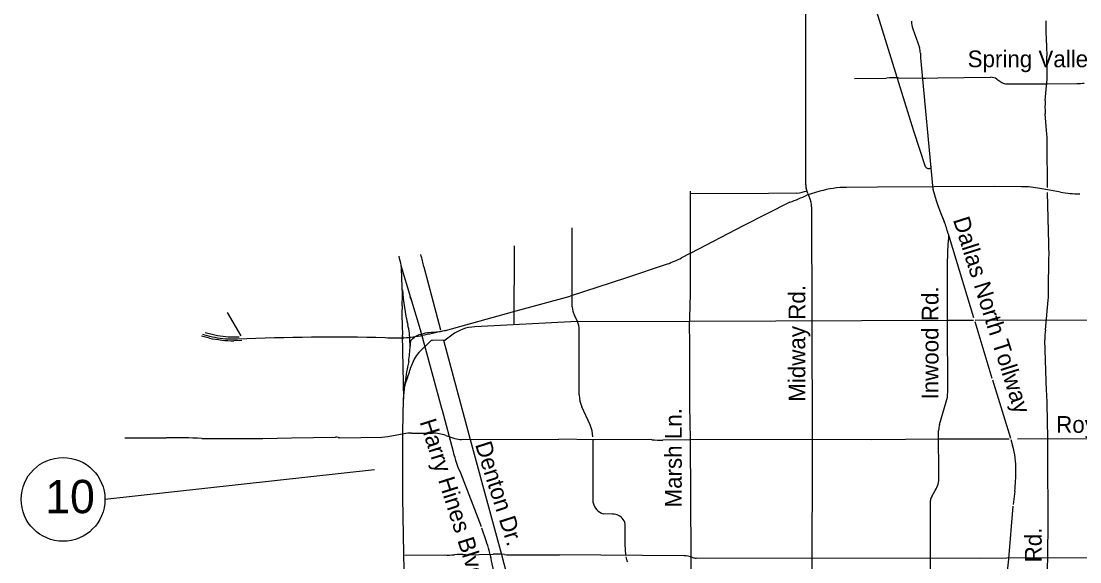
# Model space of a CAD drawing. Extents: x 105094 to 105814, y -291615 to -291123.
# Drawn here: x 105371.4 to 105448.1, y -291407.7 to -291368.5 of the extents above; entities that cross this region are included whole.
import ezdxf

# ---------------------------------------------------------------- set-up
doc = ezdxf.new("R2010")
doc.units = 0
doc.layers.add('G_BORDER', color=7, linetype='Continuous')
doc.layers.add('G_MAP', color=7, linetype='Continuous')

msp = doc.modelspace()

# ---------------------------------------------------------------- linework, layer by layer
at = {"layer": 'G_BORDER'}
msp.add_line((105396.969, -291401.024), (105377.435, -291403.157), dxfattribs=at)
msp.add_circle((105374.4, -291403.157), 3.035, dxfattribs=at)
at = {"layer": 'G_MAP'}
for p, q in [((105428.23, -291378.214), (105428.23, -291362.41)), ((105445.671, -291369), (105445.668, -291368.473)), ((105435.989, -291369.057), (105436.471, -291370.416)), ((105445.691, -291370.072), (105445.671, -291369)), ((105436.542, -291370.831), (105436.542, -291371.168)), ((105445.736, -291372.229), (105445.717, -291371.047)), ((105436.542, -291371.168), (105437.459, -291380.687)), ((105431.759, -291372.656), (105434.1, -291372.623)), ((105434.959, -291372.617), (105436.723, -291372.644)), ((105442.086, -291372.703), (105442.453, -291372.941)), ((105442.824, -291373.05), (105445.762, -291373.043)), ((105445.597, -291374.249), (105445.717, -291372.927)), ((105445.762, -291373.043), (105447.896, -291373.024)), ((105445.688, -291376.421), (105445.592, -291375.214)), ((105445.768, -291380.548), (105445.742, -291377.38)), ((105419.848, -291380.822), (105419.849, -291381.654)), ((105428.387, -291381.004), (105428.268, -291380.597)), ((105429.253, -291380.831), (105428.326, -291381.117)), ((105428.387, -291381.004), (105428.601, -291381.569)), ((105433.435, -291380.536), (105431.191, -291380.549)), ((105437.549, -291380.51), (105433.435, -291380.536)), ((105437.459, -291380.687), (105437.698, -291381.488)), ((105441.938, -291380.484), (105437.549, -291380.51)), ((105443.883, -291380.497), (105441.938, -291380.484)), ((105445.894, -291380.762), (105445.215, -291380.635)), ((105445.846, -291384.63), (105445.768, -291380.917)), ((105446.696, -291380.9), (105445.894, -291380.762)), ((105419.849, -291381.654), (105419.862, -291385.122)), ((105427.086, -291381.628), (105423.708, -291383.33)), ((105428.646, -291381.97), (105428.701, -291398.615)), ((105423.708, -291383.33), (105419.91, -291385.306)), ((105411.314, -291388.426), (105411.295, -291383.484)), ((105438.563, -291383.908), (105438.628, -291384.149)), ((105438.628, -291384.149), (105440.398, -291389.982)), ((105419.823, -291385.345), (105419.235, -291385.653)), ((105398.896, -291386.209), (105400.275, -291390.842)), ((105400.549, -291386.304), (105401.761, -291390.861)), ((105418.19, -291386.101), (105415.173, -291387.118)), ((105445.842, -291387.925), (105445.862, -291385.783)), ((105415.173, -291387.118), (105411.159, -291388.42)), ((105406.983, -291389.569), (105411.159, -291388.42)), ((105411.31, -291389.204), (105411.314, -291388.426)), ((105445.61, -291390.863), (105445.804, -291388.729)), ((105387.321, -291391.313), (105386.31, -291389.615)), ((105398.969, -291389.798), (105398.986, -291390.554)), ((105402.122, -291390.916), (105406.983, -291389.569)), ((105411.693, -291390.265), (105411.482, -291389.808)), ((105440.514, -291390.176), (105449.211, -291390.156)), ((105398.986, -291390.554), (105398.999, -291391.223)), ((105399.358, -291390.38), (105399.342, -291390.273)), ((105400.275, -291390.842), (105401.832, -291396.545)), ((105400.307, -291390.961), (105400.34, -291391.097)), ((105401.783, -291390.945), (105401.803, -291391.016)), ((105411.675, -291390.26), (105404.246, -291390.647)), ((105411.821, -291395.591), (105411.821, -291390.846)), ((105440.488, -291390.269), (105441.732, -291394.374)), ((105385.022, -291391.468), (105384.424, -291391.322)), ((105384.703, -291391.07), (105385.4, -291391.242)), ((105387.363, -291391.655), (105386.785, -291391.668)), ((105386.94, -291391.387), (105387.16, -291391.381)), ((105398.99, -291391.242), (105399.071, -291395.889)), ((105399.006, -291391.332), (105399.006, -291391.552)), ((105399.561, -291392.024), (105399.503, -291391.122)), ((105401.031, -291391.697), (105400.183, -291392.522)), ((105400.385, -291391.226), (105400.42, -291391.355)), ((105402.064, -291391.623), (105401.169, -291391.639)), ((105402.583, -291391.25), (105402.107, -291391.608)), ((105445.697, -291395.291), (105445.565, -291391.59)), ((105399.845, -291393.003), (105399.695, -291393.332)), ((105399.071, -291395.889), (105399.206, -291394.67)), ((105399.377, -291394.318), (105399.246, -291394.633)), ((105441.77, -291394.49), (105443.072, -291398.73)), ((105399.038, -291398.273), (105399.071, -291395.889)), ((105437.931, -291397.739), (105438.423, -291396.093)), ((105401.832, -291396.545), (105401.88, -291396.7)), ((105401.88, -291396.7), (105402.672, -291399.684)), ((105412.6, -291397.761), (105412.009, -291396.46)), ((105399.035, -291403.017), (105399.038, -291398.273)), ((105399.65, -291398.35), (105401.185, -291398.357)), ((105402.147, -291398.518), (105402.801, -291398.74)), ((105428.701, -291398.615), (105428.704, -291398.779)), ((105437.886, -291401.553), (105437.869, -291398.156)), ((105403.282, -291398.819), (105410.339, -291398.786)), ((105412.828, -291403.411), (105412.815, -291398.828)), ((105428.704, -291398.776), (105428.685, -291410.46)), ((105443.104, -291398.821), (105443.231, -291399.257)), ((105437.366, -291402.94), (105437.627, -291402.509)), ((105399.094, -291407.102), (105399.035, -291403.017)), ((105437.282, -291410.389), (105437.282, -291403.244)), ((105443.385, -291402.558), (105443.269, -291403.539)), ((105443.256, -291403.655), (105442.932, -291407.466)), ((105414.233, -291404.218), (105413.558, -291404.215)), ((105405.068, -291406.149), (105404.755, -291405.236)), ((105399.162, -291410.487), (105399.094, -291407.102)), ((105403.573, -291407.164), (105405.577, -291407.122)), ((105399.168, -291407.196), (105402.032, -291407.183)), ((105406.14, -291410.645), (105405.459, -291407.609)), ((105407.106, -291407.176), (105410.377, -291407.173)), ((105419.396, -291407.241), (105410.377, -291407.173)), ((105442.933, -291407.489), (105442.544, -291410.814)), ((105450.086, -291407.395), (105442.801, -291407.424))]:
    msp.add_line(p, q, dxfattribs=at)
for points in [[(105436.913, -291379.063), (105436.064, -291376.473), (105432.285, -291364.23)], [(105436.888, -291372.631), (105437.821, -291372.62), (105441.637, -291372.574)], [(105428.236, -291380.358), (105428.23, -291378.214)], [(105427.596, -291380.964), (105425.529, -291380.998), (105419.849, -291381.024)], [(105437.879, -291382.066), (105438.082, -291382.554), (105438.279, -291383.022)], [(105407.109, -291384.786), (105407.07, -291390.499)], [(105419.862, -291385.122), (105419.855, -291388.167), (105419.833, -291389.194), (105419.797, -291390.586), (105419.804, -291391.739), (105419.814, -291396.38), (105419.852, -291398.796), (105419.894, -291407.283), (105419.927, -291410.509)], [(105438.525, -291395.396), (105438.515, -291390.195), (105438.512, -291385.694)], [(105411.675, -291390.26), (105419.826, -291390.254), (105438.502, -291390.176), (105440.391, -291390.176)], [(105401.98, -291391.62), (105403.902, -291398.822), (105405.317, -291403.953), (105406.186, -291407.151), (105407.067, -291410.6)], [(105445.746, -291410.321), (105445.797, -291405.189), (105445.784, -291399.648), (105445.775, -291398.734), (105445.73, -291396.218)], [(105378.885, -291398.692), (105381.882, -291398.692)], [(105387.064, -291398.751), (105388.872, -291398.744), (105390.968, -291398.686), (105394.157, -291398.654)], [(105394.46, -291398.686), (105397.514, -291398.657), (105397.944, -291398.608), (105399.126, -291398.395)], [(105417.088, -291398.83), (105416.881, -291398.809), (105412.916, -291398.831), (105410.339, -291398.786)], [(105442.978, -291398.798), (105437.908, -291398.802), (105433.035, -291398.841), (105428.733, -291398.815), (105419.888, -291398.844), (105417.875, -291398.866)], [(105455.298, -291398.714), (105453.848, -291398.724), (105449.472, -291398.776), (105443.595, -291398.798)], [(105403.014, -291400.811), (105403.198, -291401.234), (105404.706, -291405.122)], [(105415.196, -291407.202), (105415.157, -291406.414), (105415.154, -291405.707), (105415.154, -291405.089)], [(105442.801, -291407.424), (105440.876, -291407.44), (105420.291, -291407.412)]]:
    msp.add_lwpolyline(points, dxfattribs=at)
for centre, radius, start, end in [((105437.517, -291368.517), 1.621, 179.60417, 199.45504), ((105457.605, -291370.244), 11.915, 179.16997, 183.8628), ((105435.306, -291370.831), 1.236, 359.98045, 19.59311), ((105441.647, -291373.383), 0.809, 57.11731, 90.68436), ((105442.32, -291372.483), 3.426, 352.56167, 4.25325), ((105434.595, -291381.302), 8.693, 87.6006, 93.26524), ((105436.75, -291371.528), 1.116, 268.65087, 279.25576), ((105442.822, -291372.369), 0.681, 237.13024, 270.11395), ((105447.854, -291368.986), 4.039, 270.59303, 278.00387), ((105451.329, -291374.763), 5.754, 174.87586, 184.50304), ((105435.794, -291377.468), 9.949, 0.50766, 6.04248), ((105437.149, -291378.905), 0.283, 213.85085, 303.85085), ((105427.176, -291377.367), 3.622, 276.65519, 288.54648), ((105429.099, -291380.361), 0.864, 179.76596, 195.84629), ((105431.232, -291387.623), 7.075, 90.3346, 106.24009), ((105443.859, -291387.205), 6.708, 78.33554, 89.79815), ((105448.062, -291373.009), 8.009, 260.18349, 270.29424), ((105416.991, -291355.333), 28.166, 291.00308, 293.73108), ((105427.994, -291381.841), 0.665, 348.79148, 24.09172), ((105441.542, -291380.603), 3.944, 192.96837, 201.77593), ((105425.531, -291387.601), 13.546, 15.82144, 19.75553), ((105453.9, -291385.635), 15.389, 174.00995, 180.22303), ((105436.15, -291385.343), 9.722, 357.40275, 4.20206), ((105374.133, -291391.443), 25.326, 11.96205, 13.47574), ((105363.591, -291394.572), 37.872, 12.60993, 13.98118), ((105353.561, -291389.217), 45.448, 1.55154, 3.81379), ((105415.807, -291379.103), 7.392, 288.80062, 297.62402), ((105386.265, -291388.381), 12.736, 356.67272, 2.09863), ((105439.432, -291388.019), 6.411, 353.64224, 0.8415), ((105414.897, -291386.849), 15.933, 184.05647, 193.23093), ((105397.585, -291389.533), 2.22, 14.99016, 27.63201), ((105407.768, -291389.601), 8.801, 176.86711, 181.27897), ((105412.437, -291389.211), 1.126, 179.64704, 212.00135), ((105396.268, -291391.399), 3.247, 4.88329, 16.14566), ((105404.402, -291393.671), 3.028, 92.95614, 126.91532), ((105410.435, -291390.846), 1.386, 0, 24.82111), ((105449.857, -291391.492), 4.293, 171.57539, 181.30343), ((105386.936, -291382.477), 9.193, 257.98269, 269.06123), ((105386.876, -291383.83), 7.557, 258.73374, 270.48613), ((105400.454, -291391.951), 0.895, 160.4991, 184.64113), ((105401.173, -291391.842), 0.203, 91.04299, 134.21385), ((105402.063, -291391.55), 0.0729, 271.01346, 306.89609), ((105375.169, -291390.411), 24.445, 353.51224, 356.21805), ((105401.295, -291393.664), 1.594, 134.24082, 155.49733), ((105407.779, -291395.346), 8.6, 165.36224, 175.49028), ((105396.099, -291392.96), 3.548, 337.48554, 346.24728), ((105401.59, -291394.194), 2.082, 155.54448, 169.17518), ((105400.138, -291395), 0.965, 157.62428, 175.28225), ((105413.925, -291395.591), 2.104, 180.00176, 204.4155), ((105436.107, -291395.4), 2.418, 343.33024, 0.07939), ((105433.872, -291396.167), 11.858, 359.75516, 4.23765), ((105410.483, -291398.722), 2.325, 2.32785, 24.42993), ((105439.364, -291398.167), 1.495, 163.37892, 179.56706), ((105381.847, -291479.746), 81.054, 88.15479, 89.97523), ((105394.165, -291399.467), 0.813, 76.99129, 90.53985), ((105394.448, -291398.261), 0.425, 256.41438, 271.57819), ((105399.639, -291401.285), 2.935, 89.77828, 100.07515), ((105401.173, -291401.384), 3.027, 71.21768, 89.7615), ((105386.637, -291261.433), 137.319, 269.09041, 270.17832), ((105403.276, -291397.343), 1.475, 251.22497, 270.25442), ((105417.799, -291391.957), 6.91, 264.09156, 270.63248), ((105437.707, -291400.863), 5.752, 358.01784, 16.21062), ((105422.329, -291394.329), 20.373, 195.23976, 198.55296), ((105436.088, -291401.578), 1.798, 328.83384, 0.81991), ((105432.76, -291401.301), 10.699, 353.25461, 1.27995), ((105437.868, -291403.244), 0.586, 148.83826, 180.00754), ((105413.886, -291403.184), 1.081, 192.08774, 252.36765), ((105414.229, -291405.176), 0.958, 35.57722, 89.75152), ((105414.53, -291405.024), 0.627, 354.07318, 40.27124), ((105393.974, -291409.902), 11.712, 11.2889, 18.68671), ((105405.742, -291416.092), 8.972, 85.86507, 91.05128), ((105402.331, -291403.752), 3.444, 265.02044, 277.45793), ((105403.215, -291417.05), 9.893, 87.92868, 92.53089), ((105406.884, -291404.122), 3.062, 260.69081, 274.14927), ((105415.902, -291407.296), 0.703, 182.10758, 213.24781), ((105419.385, -291409.01), 1.769, 68.64881, 89.64026), ((105420.292, -291406.684), 0.728, 248.83795, 269.88721)]:
    msp.add_arc(centre, radius, start, end, dxfattribs=at)
for points in [[(105402.122, -291390.916), (105400.604, -291391.258), (105399.292, -291391.457), (105397.752, -291391.457), (105387.044, -291391.536), (105386.164, -291391.536), (105384.676, -291391.257), (105384.536, -291391.221)], [(105399.61, -291391.652), (105399.926, -291391.362), (105400.323, -291391.18), (105400.682, -291391.087), (105401.212, -291391.033), (105402.122, -291390.916)]]:
    msp.add_spline(points, degree=3, dxfattribs=at)

# ---------------------------------------------------------------- texts
at = {"layer": 'G_BORDER'}
msp.add_text('10', height=2.416, dxfattribs=at).set_placement((105373.111, -291404.159))
at = {"layer": 'G_MAP'}
for s, height, p in [('Spring Valley Rd.', 1.21107, (105439.971, -291371.842)), ('Royal Ln.', 1.2111, (105446.389, -291398.334))]:
    msp.add_text(s, height=height, dxfattribs=at).set_placement(p)
for s, height, rotation, p in [('Dallas North Tollway', 1.21107, 287.67121, (105438.897, -291382.894)), ('Midway Rd.', 1.2111, 90, (105428.202, -291396.082)), ('Inwood Rd.', 1.2111, 90, (105437.858, -291395.92)), ('Marsh Ln.', 1.2111, 90, (105419.247, -291403.744)), ('Harry Hines Blvd.', 1.21107, 287.67121, (105400.24, -291397.539)), ('Denton Dr.', 1.2111, 287.67121, (105404.254, -291399.178)), ('Preston Rd.', 1.21107, 90, (105445.337, -291413.751))]:
    msp.add_text(s, height=height, rotation=rotation, dxfattribs=at).set_placement(p)

doc.saveas('drawing.dxf')
